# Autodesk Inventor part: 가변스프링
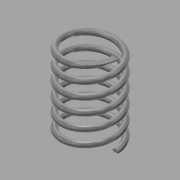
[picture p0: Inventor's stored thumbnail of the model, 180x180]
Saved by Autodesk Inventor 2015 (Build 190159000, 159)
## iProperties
Created: 2015-10
Part Number: 가변스프링
Material: Steel, Mild
Document SubType Name: Modeling
Designer: youjin13
Mass: 128.859 g
Surface Area: 133.055 cm^2
Volume: 16.4151 cm^3
Density: 7.85 g/cm^3
Appearance: Semi-Polished
Author: youjin13
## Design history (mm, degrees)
sketch "Sketch2"
  geometry: L1 (0, 0)-(-22.5, 0); L2 (-22.5, 0)-(-22.5, 73.25); L3 (-22.5, 73.25)-(0, 73.25); L4 (0, 73.25)-(0, 0); C1 r 2.5 at (-22.5, 0)
  constraints: 8 end point, 2 parallel, 1 centre point, 1 coincident, 1 horizontal, 1 perpendicular
  dimensions: "d0" = 73.25 distance of L1.end L2.end (derived); "d1" = 45 diameter of L2 L4; "d2" = 2.5 radius of C1
coil "Coil1" pitch "d3" = 10; turns "d5" = 6; dims "d4" = 73.25 (= d0), "d6" = 0, angle "d7" = 90 deg, angle "d8" = 90 deg, "d9" = 0, "d10" = 0
sketch "Sketch3"
  geometry: L1 (-90.117, 52.886)-(93.925, 52.886); L2 (93.925, 52.886)-(93.925, -99.425); L3 (93.925, -99.425)-(-90.117, -99.425); L4 (-90.117, -99.425)-(-90.117, 52.886); 1 further point
  constraints: 8 end point, 2 parallel, 1 horizontal, 1 perpendicular
extrude "Extrusion1" cut sketch "Sketch3" stored distance "d11" = 0; taper "d12" = 0 deg
workplane "Work Plane1"
sketch "Sketch4"
  geometry: L1 (64.226, 57.162)-(-64.986, 57.162); L2 (-64.986, 57.162)-(-64.986, -45.522); L3 (-64.986, -45.522)-(64.226, -45.522); L4 (64.226, -45.522)-(64.226, 57.162); 1 further point
  constraints: 8 end point, 2 parallel, 1 horizontal, 1 perpendicular
extrude "Extrusion2" cut sketch "Sketch4" stored distance "d13" = 0; taper "d14" = 0 deg
body "Solid1"
